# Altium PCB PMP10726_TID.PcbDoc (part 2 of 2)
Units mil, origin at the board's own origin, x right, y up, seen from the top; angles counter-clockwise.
Board outline 1200 x 2800 mil, 4 copper layers (Top Layer, Inner Layer 1, Inner Layer 2, Bottom Layer), stack 60.2 mil thick; 86 components, 43 nets, 209 pads, 170 vias.
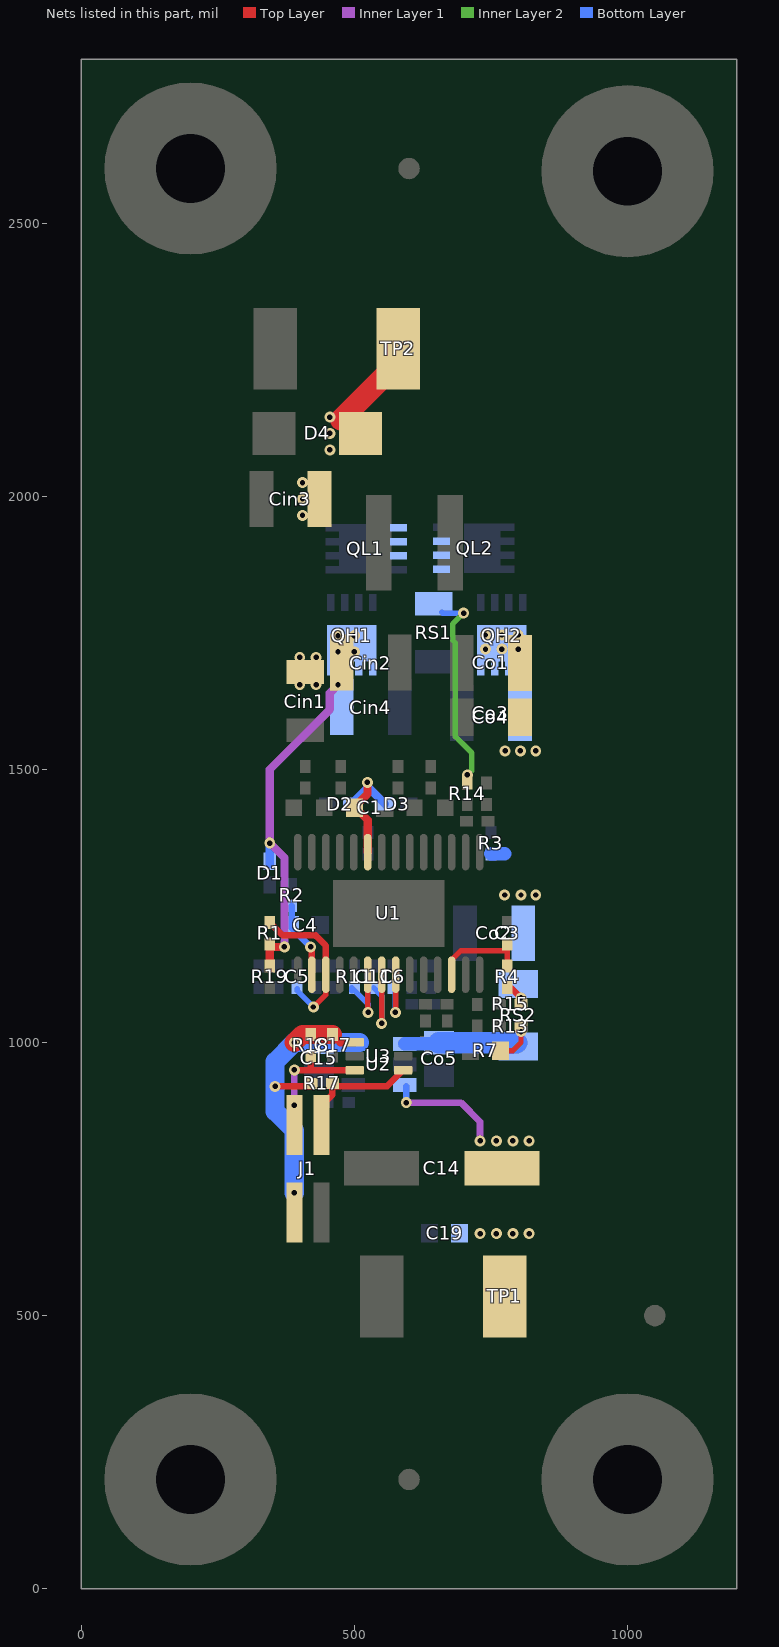
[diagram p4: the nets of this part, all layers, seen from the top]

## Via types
v1: diameter 20, hole 10, Top Layer to Bottom Layer, 93 vias
v2: diameter 20, hole 10, Top Layer to Bottom Layer, tented both sides, 77 vias

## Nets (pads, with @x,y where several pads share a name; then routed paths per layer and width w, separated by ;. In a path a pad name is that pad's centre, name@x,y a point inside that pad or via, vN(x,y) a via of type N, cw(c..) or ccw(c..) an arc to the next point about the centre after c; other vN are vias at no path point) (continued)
PP_IN: Cin1.1 Cin2.1 Cin3.1 Cin4.1 D1.2 D4.1 QH1.5 QH1.6 QH1.7 QH1.8 QH1.9 R1.2 R19.1 TP2.1 | length 758.4
  Top Layer w15: R19.1@345,1139.68 R1.2@345,1180.31 ; R1.2@350.31,1175 v2(371.87,1175)
  Top Layer w40: D4.1@475,2140 TP2.1@556.26,2221.26
  Inner Layer 1 w15: v2(371.87,1175) 371.87,1338.19 345,1365.06 345,1500 455,1610 455,1640 v1(470,1655)
  Bottom Layer w15: D1.2@345,1326.65 D1.2@345,1331.65 v1(345,1365)
  other v1: 400,1655 430,1655 400,1705 430,1705 470,1715 500,1715 470,1745 500,1745 405,1965 405,1995 405,2025 455,2085 455,2115 455,2145
PP_OUT: C14.1 C19.2 Co5.1 R7.2 R13.1 RS2.2 TP1.1 U2.1 U2.3 | length 474.5
  Top Layer w10: R7.2@767.56,985 790,985 805,1000 v1(805,1020)
  Inner Layer 1 w12: v1(595,890) 695,890 730,855 v2(730,820)
  Bottom Layer w12: v1(595,890) U2.3@595,919.84
  Bottom Layer w25: U2.1@592.24,997.4 Co5.1@647.13,997.4
  Bottom Layer w40: Co5.1@655,999.53 RS2.2@796.61,999.53
  other v2: 730,650 760,650 790,650 820,650 760,820 790,820 820,820
RT: R11.1 U1.6 | length 127.4
  Top Layer w10: U1.6@524.43,1124.09 524.43,1064.43 525,1063.86 v1@525,1060
  Bottom Layer w10: R11.1@495,1095 495,1100.31 497.5,1097.82 525,1070.31 v1(525,1055)
SCL: J1.2 R18.1 U3.3 | length 205.1
  Top Layer w12: v1(390,950) 390.59,949.41 U3.3@500.71,949.41 ; 420,950.32 R18.1@420,975.32
  Inner Layer 1 w12: v1(390,885) 395,890 390,895 v1(390,950)
SDA: J1.4 R17.1 U3.4 | length 229.8
  Top Layer w12: J1.4@440,840.12 J1.4@440,849.12 440,885 459.68,904.68 459.68,920 559.88,920 U3.4@589.29,949.41
SLOPE: C11.1 U1.7 | length 150.6
  Top Layer w10: 550,1045 U1.7@550.02,1124.09
  Bottom Layer w10: C11.1@535,1100.32 550,1085.32 v1(550,1035)
SS: C6.2 U1.8 | length 108
  Top Layer w10: v1@575.61,1060.61 U1.8@575.61,1124.09 U1.8@575.61,1133.31
  Bottom Layer w10: v1@575,1060 C6.2@575,1095.31
  other v1: 575,1055
SYSTEM_3V3: C15.2 C17.2 J1.1 R17.2 R18.2 U2.5 U3.1 | length 611.5
  Top Layer w12: v1@355,920 R17.2@420.31,920
  Top Layer w15: C17.2@460,1014.69 474.09,1000.59 U3.1@500.71,1000.59
  Top Layer w35: v1(390,1000) 404.69,1014.69 R18.2@420,1014.69 C17.2@460,1014.69
  Bottom Layer w35: v1(390,725) 390,839.04 355,874.04 v1(355,919.52) 355,965 v1(390,1000) 435,1000 497.76,1000 U2.5@509.57,1000
VCC: C1.1 D2.2 D3.2 U1.23 | length 245.5
  Top Layer w15: v1(523.82,1476.3) 523.82,1454.86 500.26,1431.3 501,1430.56 524.43,1407.13 U1.23@524.43,1348.5
  Bottom Layer w15: D2.2@494.47,1436.3 523.82,1465.65 v1@523.82,1468.65 ; v1(523.82,1476.3) v1@523.82,1468.65 ; D3.2@556.16,1436.3 v1@523.82,1468.65
VIN_IC: C4.2 R2.1 U1.2 | length 138.7
  Top Layer w12: U1.2@422.07,1124.09 v2@422.07,1172.93
  Bottom Layer w12: R2.1@385,1250.32 385,1215 385,1210 v2(420,1175)
VINSNS: C5.2 R1.1 U1.3 | length 291.8
  Top Layer w10: v1(425,1065) 447.66,1087.66 U1.3@447.66,1124.09
  Top Layer w12: R1.1@345,1219.68 368.68,1196 428.7,1196 ; U1.3@447.66,1124.09 447.66,1177.34 430,1195 ; 428.7,1196 429,1196 430,1195 ; 428.7,1196 429.7,1195 430,1195
  Bottom Layer w10: C5.2@395,1098.35 395,1095 v1(425,1065) ; v1@428.35,1065 v1@430,1063.35
VOSNS: C3.2 R4.1 U1.12 | length 173.7
  Top Layer w10: U1.12@677.97,1124.09 677.97,1151.46 694.82,1168.3 776.7,1168.3 ; R4.1@780,1139.68 C3.2@780,1180.31
VOUT: Co1.1 Co2.1 Co3.1 Co4.1 QH2.5 QH2.6 QH2.7 QH2.8 QH2.9 R3.2 R4.2 R15.1 RS2.1 | length 50.9
  Top Layer w12: R4.2@786.5,1100.31 v1(805,1081.81)
  Bottom Layer w25: R3.2@750,1345.31 774.69,1345.31
  other v1: 776,1534 804,1534 832,1534 740,1720 770,1720 800,1720 740,1746 770,1746 800,1746
  other v2: 775,1270 805,1270 832,1270
VRS: QL1.1 QL1.2 QL1.3 QL2.1 QL2.2 QL2.3 R14.2 RS1.2 | length 362.8
  Inner Layer 2 w10: v2(700,1786) 680,1766 680,1736.72 685,1731.72 685,1560 715,1530 715,1498.19 v1(706.81,1490)
  Bottom Layer w10: RS1.2@660.2,1787.95 662.15,1786 v2(700,1786)
pads on no net: FID1.1 FID2.1 FID3.1 H1.1 H2.1 H3.1 H4.1

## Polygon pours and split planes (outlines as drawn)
GND on Bottom Layer "Bottom Layer-No Net 5" (solid, remove dead copper, pour order 45): 300,2175 850,2175 850,625 300,625
PP_IN on Bottom Layer "Bottom Layer-No Net 4" (solid, remove dead copper, pour order 38): 550,1770 390,1770 390,1560 525,1560 525,1668.15 526.05,1668.15 550,1678.07
HDRV1_N on Bottom Layer "Bottom Layer-No Net 3" (solid, remove dead copper, pour order 36): 640,2175 640,1970 615,1970 615,1955 545,1955 545,1830 525.55,1830 520,1824.45 520,1780 445,1780 430,1780 430,2030 475,2075 475,2175
VRS on Bottom Layer "Bottom Layer-No Net 2" (solid, remove dead copper, pour order 35): 555,1951 604,1951 629.85,1925.15 685,1925.15 685,1785 605,1785 605,1865 600,1870 555,1870
HDRV2_N on Bottom Layer "Bottom Layer-No Net 1" (solid, remove dead copper, pour order 34): 690,1960 690,1835 720,1805 720,1790 720,1785 795,1785 795,1824.13 790,1829.13 790,1850 800,1860 850,1860 850,2175 650,2175 650,1970 660,1960
VOUT on Bottom Layer "Bottom Layer-No Net" (solid, remove dead copper, pour order 27): 760,1155 760,1080 850,1080 850,1775 720,1775 720,1670.12 759.88,1670.12
PP_OUT on Bottom Layer "Bottom Layer-No Net 6" (solid, remove dead copper, pour order 42): 850,625 705,625 705,1020 850,1020
GND on Inner Layer 1 "Bottom Layer-No Net 5" (solid, remove dead copper, pour order 46): 300,2175 850,2175 850,625 300,625
HDRV2_N on Inner Layer 1 "Inner Layer 2-No Net" (solid, remove dead copper, pour order 40): 850,2175 650,2175 650,1830 790,1830 790,1845 805,1860 850,1860
HDRV1_N on Inner Layer 1 "Top Layer-No Net" (solid, remove dead copper, pour order 30): 615,2175 640,2175 640,2075 640,1970 610,1970 610,1855 575,1855 575,1830 480,1830 480,1992.05 545,2057.05 545,2175
PP_IN on Inner Layer 1 "Top Layer-No Net 1" (solid, remove dead copper, pour order 32): 377.6,1640 488.11,1640 488.11,1665 514.95,1693 515.05,1820 467.6,1820 467.6,1995 477.6,2005 532.68,2060.08 532.68,2175 427.6,2175 417.6,2165 417.6,2070 377.6,2030 377.6,1830
VOUT on Inner Layer 1 "Bottom Layer-No Net" (solid, remove dead copper, pour order 26): 760,1155 760,1080 850,1080 850,1820 720,1820 720,1670.12 759.88,1670.12
GND on Inner Layer 2 "Bottom Layer-No Net 5" (solid, remove dead copper, pour order 43): 300,2175 850,2175 850,625 300,625
HDRV2_N on Inner Layer 2 "Inner Layer 2-No Net" (solid, remove dead copper, pour order 39): 850,2175 650,2175 650,1830 790,1830 790,1845 805,1860 850,1860
HDRV1_N on Inner Layer 2 "Top Layer-No Net" (solid, remove dead copper, pour order 29): 615,2175 640,2175 640,2075 640,1970 610,1970 610,1855 575,1855 575,1830 480,1830 480,1992.05 545,2057.05 545,2175
VOUT on Inner Layer 2 "Bottom Layer-No Net" (solid, remove dead copper, pour order 25): 760,1155 760,1080 850,1080 850,1820 720,1820 720,1670.12 759.88,1670.12
PP_IN on Inner Layer 2 "Bottom Layer-No Net 4" (solid, remove dead copper, pour order 37): 515,1760 390,1760 390,1642.17 515,1642.17
PP_IN on Top Layer "Top Layer-No Net 3" (solid, remove dead copper, pour order 49): 435,2350 620,2350 620,2195 560,2195 560,2183 541.99,2164.99 435,2164.99
GND on Top Layer "Bottom Layer-No Net 5" (solid, remove dead copper, pour order 44): 300,2175 850,2175 850,625 300,625
HDRV1_N on Top Layer "Top Layer-No Net" (solid, remove dead copper, pour order 28): 615,2175 640,2175 640,2075 640,1970 610,1970 610,1855 575,1855 575,1830 480,1830 480,1992.05 559,2071.05 559,2175
HDRV2_N on Top Layer "Top Layer-No Net 2" (solid, remove dead copper, pour order 33): 650,1825 790,1825 790,1850 800,1860 850,1860 850,2175 650,2175
PP_IN on Top Layer "Top Layer-No Net 1" (solid, remove dead copper, pour order 31): 380,1640 514.8,1640 537.76,1675 554.89,1675 554.97,1785.02 525.02,1815 470,1815 470,1995 480,2005 550,2075 550,2175 430,2175 420,2165 420,2070 380,2030 380,1830
VOUT on Top Layer "Bottom Layer-No Net" (solid, remove dead copper, pour order 24): 759.91,1525 850,1525 850,1820 715,1820 715,1670.12 759.88,1670.12
PP_OUT on Top Layer "Bottom Layer-No Net 6" (solid, remove dead copper, pour order 41): 850,625 705,625 705,845 850,845

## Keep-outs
Keep-Out Layer:
  lines w5: -2.5,0 ccw(c0,0) 0,-2.5 ; -2.5,0 ccw(c0,0) 0,-2.5 ; -2.5,0 -2.5,2800 ; -2.5,2800 cw(c0,2800) 0,2802.5 ; -2.5,2800 cw(c0,2800) 0,2802.5 ; 0,-2.5 1200,-2.5 ; 0,2802.5 1200,2802.5 ; 1200,-2.5 ccw(c1200,0) 1202.5,0 ; 1200,-2.5 ccw(c1200,0) 1202.5,0 ; 1200,2802.5 cw(c1200,2800) 1202.5,2800 ; 1200,2802.5 cw(c1200,2800) 1202.5,2800 ; 1202.5,0 1202.5,2800
  text ".Layer_Name" at 577,-858.49 h60

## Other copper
Top Layer:
  rectangle net GND: 299.29,2175 404.32,2350
  rectangle net GND: 490,450 610,625
  rectangle net PP_OUT: 705,450 850,625
  text ".Layer_Name" at 577,-858.49 h60
Inner Layer 1:
  text ".Layer_Name" at 577,-858.49 h60
Inner Layer 2:
  text ".Layer_Name" at 577,-858.49 h60
Bottom Layer:
  text ".Layer_Name" at 577,-858.49 h60

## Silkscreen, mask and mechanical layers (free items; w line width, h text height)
Top Overlay:
  lines w10: 300,625 300,2175 850,2175 850,625 300,625
  text "TI" at 1079.82,1008.16 h60 r90
  text "SCL" at 355,826 h20 r90
  text "SDA" at 489,824 h20 r90
  text ".CopyrightYear" at 1079.82,732.16 h60 r90
  text "GND" at 489,670 h20 r90
  text "3.3V" at 355,660 h20 r90
  text "©" at 1083.34,615.16 h105 r90
  text ".Layer_Name" at 577,-858.49 h60
Bottom Overlay:
  lines w10: 300,625 850,625 850,2175 300,2175 300,625
  text "UL94V-0" at 975,2170 h60 r90
  text "MADE IN U.S." at 1075,2170 h60 r90
  text ".Layer_Name" at 577,-858.49 h60
Top Paste:
  text ".Layer_Name" at 577,-858.49 h60
Bottom Paste:
  text ".Layer_Name" at 577,-858.49 h60
Top Solder:
  text ".Layer_Name" at 577,-858.49 h60
  text ".Layer_Name" at 577,-858.49 h60
Bottom Solder:
  text ".Layer_Name" at 577,-858.49 h60
Drill Guide:
  text ".Layer_Name" at 577,-858.49 h60
Mechanical 1:
  the board outline again, w10
  text ".Layer_Name" at 577,-858.49 h60
Mechanical 2:
  rectangle: 125,-400 500,-275
  rectangle: 0,-275 125,-150
  lines w7: 0,-275 1000,-275 ; 125,-400 125,-150 ; 250,-400 250,-150 ; 500,-400 500,-150 ; 750,-400 750,-150 ; 0,-400 0,-150 1000,-150 1000,-400 0,-400
  text ".Layer_Name" at 577,-858.49 h60
Mechanical 3:
  text ".Layer_Name" at 577,-858.49 h60
Mechanical 4:
  text ".Layer_Name" at 577,-858.49 h60
Mechanical 5:
  lines w10: -292,-930.17 6308,-930.17 ; -292,-726.83 6310,-726.83 ; -292,-523.5 -292,-1133.5 3713,-1133.5 6310,-1133.5 6310,-523.5 -291.5,-523.5 -291.5,-1133.5 1284,-1133.5 ; 2173,-1133.5 2173,-523.5 ; 3440,-726.83 3440,-523.5 ; 4280,-726.83 4280,-523.5 ; 4902,-1140 4902,-937.17
  text "COMPONENTS MARKED 'DNP' SHOULD NOT BE POPULATED." at 1153.5,-318.5 h60
  text "ASSEMBLY VARIANT:" at 1153,-434 h60
  text ".VariantName" at 2189,-434 h60
  text "PCB VIEWED FROM TOP SIDE" at -228.5,-655.67 h60
  text "BOARD #:" at 2248,-655.67 h60
  text ".PRJ_Number" at 2793.5,-655.67 h60
  text "REV:" at 3638,-655.67 h60
  text ".PCB_Rev" at 3929.5,-655.67 h60
  text "SVN REV:" at 4476,-655.67 h60
  text ".VersionControl_RevNumber" at 4982,-655.67 h60
  text "TID #:" at 2248,-859 h60
  text ".TID" at 2793.5,-859 h60
  text "PLOT NAME =" at -228.5,-1064.34 h60
  text ".plot_File_Name" at 577,-1064.34 h60
  text "GENERATED    :" at 2250,-1064.34 h60
  text ".Print_Date" at 3119.5,-1064.34 h60
  text ".Print_Time" at 3848.5,-1064.34 h60
  text "TEXAS INSTRUMENTS" at 5113,-1064.34 h60
Mechanical 6:
  lines w10: -292.5,-727.33 6309.5,-727.33 ; -290.5,-930.67 6309.5,-930.67 ; 1115.5,-1140.5 1115.5,-937.67 ; 1737.5,-727.33 1737.5,-524 ; 2577.5,-727.33 2577.5,-524 ; 3844.5,-1134 3844.5,-524 ; 4733.5,-1134 6309,-1134 6309,-524 -292.5,-524 -292.5,-1134 2304.5,-1134 6309.5,-1134 6309.5,-524
  text "COMPONENTS MARKED 'DNP' SHOULD NOT BE POPULATED." at 6102,-318 h60
  text ".VariantName" at 5058,-434 h60
  text "ASSEMBLY VARIANT:" at 6097,-434 h60
  text ".VersionControl_RevNumber" at 1035.5,-656.17 h60
  text "SVN REV:" at 1541.5,-656.17 h60
  text ".PCB_Rev" at 2088,-656.17 h60
  text "REV:" at 2379.5,-656.17 h60
  text ".PRJ_Number" at 3224,-656.17 h60
  text "BOARD #:" at 3769.5,-656.17 h60
  text "PCB VIEWED FROM BOTTOM SIDE" at 6246,-656.17 h60
  text ".PRJ_Number" at 3224,-859.5 h60
  text "TID #:" at 3769.5,-859.5 h60
  text "TEXAS INSTRUMENTS" at 904.5,-1064.84 h60
  text ".Print_Time" at 2169,-1064.84 h60
  text ".Print_Date" at 2898,-1064.84 h60
  text "GENERATED    :" at 3767.5,-1064.84 h60
  text ".plot_File_Name" at 5440.5,-1064.84 h60
  text "PLOT NAME =" at 6246,-1064.84 h60
Mechanical 9:
  drawing of 57 lines, arcs and shapes, not listed
  text "1" at 739.84,8036.5 h70
  text "2" at 3235.5,8036.5 h70
  text "3" at 5724.84,8036.5 h70
  text "4" at 8231.51,8036.5 h70
  text "5" at 10730.5,8036.5 h70
  text "6" at 13235.5,8036.5 h70
  text "A" at -416.5,6893.5 h70
  text "A" at 14383.5,6893.5 h70
  text "B" at -416.5,4513.5 h70
  text "B" at 14383.5,4513.5 h70
  text "C" at -416.5,2138.5 h70
  text "C" at 14383.5,2138.5 h70
  text "PROJECT TITLE:" at 11343.5,277.5 h45
  text ".PRJ_Title" at 11393.5,144.17 h70
  text "DESIGNED FOR:" at 11343.5,-23.5 h45
  text ".PRJ_Customer" at 11393.5,-163.5 h70
  text "D" at -416.5,-231.5 h70
  text "D" at 14383.5,-231.5 h70
  text "FILE NAME:" at 11343.5,-323.5 h45
  text ".PCB_File_Name_No_Path" at 11393.5,-443.5 h70
  text "Texas Instruments (TI) and/or its licensors do not warrant the accuracy or completeness of this specification" at 6374,-605.34 h45
  text "ENGINEER:" at 11343.5,-613.5 h45
  text "LAYOUT BY:" at 12848.5,-613.5 h45
  text "or any information contained therein. TI and/or its licensors do not warrant that this design will meet" at 6329.01,-718 h45
  text ".PRJ_Engineer" at 11393.5,-768.49 h70
  text ".PCB_Layout" at 12899,-768.49 h70
  text "the specifications, will be suitable for your application or fit for any particular purpose, or will operate in" at 6329.01,-830.67 h45
  text ".Layer_Name" at 577,-858.49 h60
  text "ALTIUM DESIGNER VERSION:" at 12848.5,-923.5 h45
  text "an implementation. TI and/or its licensors do not warrant that the design is production worthy. You should" at 6329.01,-943.33 h45
  text "completely validate and test your design implementation to confirm the system functionality for your application." at 6374,-1056 h45
  text ".print_Scale" at 11393.5,-1056.83 h70
  text ".Application_BuildNumber" at 12899,-1056.83 h70
  text "1" at 739.84,-1263.5 h70
  text "2" at 3235.5,-1263.5 h70
  text "3" at 5724.84,-1263.5 h70
  text "4" at 8231.51,-1263.5 h70
  text "5" at 10730.5,-1263.5 h70
  text "6" at 13235.5,-1263.5 h70
Mechanical 10:
  drawing of 185 lines, arcs and shapes, not listed
  text "DESIGN INFORMATION" at 12381.02,5910 h60
  text "MIN. TRACK WIDTH:" at 11736.46,5730 h60
  text "10" at 12832.7,5730 h60
  text "MIL" at 12987.46,5730 h60
  text "MIN. CLEARANCE:" at 11736.46,5598 h60
  text "0.13" at 12772.7,5598 h60
  text "mm" at 12987.46,5598 h60
  text "MIN. VIA PAD SIZE:" at 11736.46,5466 h60
  text "20" at 12802.71,5466 h60
  text "MIL" at 12987.46,5466 h60
  text "0.127mm (5MIL)" at 12431.46,5324.29 h60
  text "MINIMUM ANNULAR RING" at 11407.23,5320 h60
  text "EXTERNAL" at 13139.46,5320 h60
  text "PER" at 11607.23,5202 h60
  text "IPC-D-275 CLASS 2 LEVEL C" at 11827.23,5202 h60
  text "MIL, HOLES" at 13315.46,5089.71 h60
  text "+/-" at 12923,5089 h60
  text "+/-" at 13777,5089 h60
  text "REGISTRATION TOLERANCES:" at 11407.23,5084 h60
  text "METAL" at 12607,5084 h60
  text "5" at 13183.2,5084 h60
  text "3" at 14016.2,5084 h60
  text "MIL" at 14132.46,5084 h60
  text "MATERIAL:" at 11332.46,4874.54 h60
  text "FR-4 High Tg" at 12318.9,4734.21 h60
  text "X" at 13055,4730 h60
  text "FR-408" at 11753.46,4725.64 h60
  text "OTHER" at 13241.46,4725.64 h60
  text "FR-4" at 13643.9,4724.21 h60
  text "62 MIL (1.6mm) +/-10%" at 12073.56,4562.92 h60
  text "THICKNESS:" at 11407.23,4558.64 h60
  text "X" at 11945.4,4558.64 h60
  text "OTHER" at 13358.46,4558.64 h60
  text "TOLERANCE:" at 11407.23,4400.64 h60
  text "X" at 12246.53,4400.64 h60
  text "ANSI IPC-6012 TYPE 3 CLASS 2" at 12433.48,4400.64 h60
  text "OTHER +/-" at 12433.46,4244.64 h60
  text "BOW & TWIST:" at 11407.23,4087.64 h60
  text "X" at 12246.53,4087.64 h60
  text "ANSI IPC-6012 TYPE 3 CLASS 2" at 12433.48,4087.64 h60
  text "OTHER +/-" at 12433.46,3929.13 h60
  text "DRILLING:" at 11332.46,3790.64 h60
  text "REFERENCE:" at 11407.23,3673.64 h60
  text "X" at 12055.46,3673.64 h60
  text "AS SHOWN" at 12242.46,3673.64 h60
  text "X" at 12956.46,3673.64 h60
  text "NC_DRILL FILES" at 13093.46,3673.64 h60
  text "PTH MIN COPPER THICKNESS:" at 11407.23,3515.64 h60
  text "X" at 12757.46,3515.64 h60
  text "1MIL" at 12894.46,3515.64 h60
  text "OTHER" at 13391.46,3515.64 h60
  text "BOARD FINISH:" at 11332.46,3356.64 h60
  text "SILKSCREEN:" at 11487.68,3238.64 h60
  text "X" at 12436.46,3238.64 h60
  text "TOP" at 12562.46,3238.64 h60
  text "X" at 12946.46,3238.64 h60
  text "BOTTOM" at 13073.46,3238.64 h60
  text "SILKSCREEN COLOR:" at 11487.68,3071.64 h60
  text "X" at 12435.42,3071.64 h60
  text "WHITE" at 12562.46,3071.64 h60
  text "OTHER" at 13073.46,3071.64 h60
  text "SOLDER RESIST COLOR:" at 11487.68,2901.64 h60
  text "X" at 12055.42,2742.44 h60
  text "GREEN" at 12182.46,2742.44 h60
  text "BLUE" at 12773.46,2742.44 h60
  text "OTHER" at 13311.46,2742.44 h60
  text "IMMERSION GOLD (ENIG)" at 12393.46,2553.92 h60
  text "ENEPIG" at 13731,2550.64 h60
  text "SURFACE FINISH:" at 11332.46,2549.64 h60
  text "X" at 12206.51,2549.64 h60
  text "IMM. TIN/SILVER OR EQUIV" at 11662,2392.64 h60
  text "OTHER" at 13093.46,2392.64 h60
  text "ARRAY/PANEL:" at 11332.46,2213.64 h60
  text "CUT AND TRIM PER MECH LAYER 1" at 12393.46,2209.35 h60
  text "N.C. ROUTE" at 12393.46,2057.64 h60
  text "X" at 13072.46,2057.64 h60
  text "V. SCORE" at 13259.46,2057.64 h60
  text "CERTIFICATION:" at 11332.46,1920.64 h60
  text "MATERIALS AND WORKMANSHIP FOR ALL PCBS" at 12057.46,1920.64 h60
  text "TO MEET OR EXCEED THE REQUIREMENTS OF:" at 12057.46,1822.64 h60
  text "X" at 11683.96,1686.13 h60
  text "ANSI IPC-A-600F CLASS ->" at 11822.96,1686.13 h60
  text "X" at 13462.02,1686.13 h60
  text "2" at 13580.96,1686.14 h60
  text "1" at 13265.96,1684.64 h60
  text "3" at 13934.96,1684.64 h60
  text "X" at 11686.02,1526.64 h60
  text "UL 94V-0" at 11822.96,1526.64 h60
  text "X" at 12498.02,1526.64 h60
  text "RoHS" at 12634.96,1526.64 h60
  text "OTHER" at 13279.36,1526.64 h60
  text "PER ORDER" at 13676.42,1526.64 h60
  text "ADDITIONAL REQUIREMENTS:" at 11332.46,1385.64 h60
  text "MICROSECTION:" at 11407.23,1270.64 h60
  text "YES" at 12312.96,1270.64 h60
  text "REQUIRED" at 13174.46,1114.49 h60
  text "BARE BOARD ELEC. TEST:" at 11407.23,1111.64 h60
  text "NONE" at 12712.96,1111.64 h60
  text "X" at 13047.46,1111.64 h60
  text "PER ORDER" at 13766.46,1111.64 h60
  text "MANUFACTURER'S UL:" at 11407.23,954.64 h60
  text "RAIL" at 12572.96,950.35 h60
  text "METAL" at 13064.77,950.35 h60
  text "X" at 13440,950 h60
  text "SILK" at 13576.46,950.35 h60
  text ".Layer_Name" at 577,-858.49 h60
Mechanical 11:
  lines w10: -292,-930.17 6308,-930.17 ; -292,-726.83 6310,-726.83 ; -292,-523.5 -292,-1133.5 3713,-1133.5 6310,-1133.5 6310,-523.5 -291.5,-523.5 -291.5,-1133.5 1284,-1133.5 ; 2173,-1133.5 2173,-523.5 ; 3440,-726.83 3440,-523.5 ; 4280,-726.83 4280,-523.5 ; 4902,-1140 4902,-937.17
  text "ALL ARTWORK VIEWED FROM TOP SIDE" at -228.5,-655.67 h60
  text "BOARD #:" at 2248,-655.67 h60
  text ".PRJ_Number" at 2793.5,-655.67 h60
  text "REV:" at 3638,-655.67 h60
  text ".PCB_Rev" at 3929.5,-655.67 h60
  text "SVN REV:" at 4476,-655.67 h60
  text ".VersionControl_RevNumber" at 4982,-655.67 h60
  text "LAYER NAME =" at -228.5,-858.49 h60
  text "TID #:" at 2248,-859 h60
  text ".TID" at 2793.5,-859 h60
  text "PLOT NAME =" at -228.5,-1064.34 h60
  text ".plot_File_Name" at 577,-1064.34 h60
  text "GENERATED    :" at 2250,-1064.34 h60
  text ".Print_Date" at 3119.5,-1064.34 h60
  text ".Print_Time" at 3848.5,-1064.34 h60
  text "TEXAS INSTRUMENTS" at 5113,-1064.34 h60
Mechanical 12:
  drawing of 295 lines, arcs and shapes, not listed
  text "Layer" at 9795.09,7860 h60
  text "Name" at 10205,7860 h60
  text "Material" at 11134.74,7860 h60
  text "Thickness" at 11994.51,7860 h60
  text "Constant" at 12644.35,7860 h60
  text "Board Layer Stack" at 13214.21,7860 h60
  text "1" at 9795.09,7740 h60
  text "Top Overlay" at 10205,7740 h60
  text "2" at 9795.09,7620 h60
  text "Top Solder" at 10205,7620 h60
  text "Solder Resist" at 11134.74,7620 h60
  text "0.50mil" at 11994.51,7620 h60
  text "3.5" at 12644.35,7620 h60
  text "3" at 9795.09,7500 h60
  text "Top Layer" at 10205,7500 h60
  text "Copper" at 11134.74,7500 h60
  text "2.80mil" at 11994.51,7500 h60
  text "4" at 9795.09,7380 h60
  text "Dielectric 1" at 10205,7380 h60
  text "FR-4" at 11134.74,7380 h60
  text "9.10mil" at 11994.51,7380 h60
  text "4.2" at 12644.35,7380 h60
  text "5" at 9795.09,7260 h60
  text "Inner Layer 1" at 10205,7260 h60
  text "Copper" at 11134.74,7260 h60
  text "2.80mil" at 11994.51,7260 h60
  text "6" at 9795.09,7140 h60
  text "Dielectric 2" at 10205,7140 h60
  text "FR-4" at 11134.74,7140 h60
  text "30.80mil" at 11994.51,7140 h60
  text "4.2" at 12644.35,7140 h60
  text "7" at 9795.09,7020 h60
  text "Inner Layer 2" at 10205,7020 h60
  text "Copper" at 11134.74,7020 h60
  text "2.80mil" at 11994.51,7020 h60
  text "8" at 9795.09,6900 h60
  text "Dielectric 3" at 10205,6900 h60
  text "FR-4" at 11134.74,6900 h60
  text "9.10mil" at 11994.51,6900 h60
  text "4.2" at 12644.35,6900 h60
  text "9" at 9795.09,6780 h60
  text "Bottom Layer" at 10205,6780 h60
  text "Copper" at 11134.74,6780 h60
  text "2.80mil" at 11994.51,6780 h60
  text "10" at 9795.09,6660 h60
  text "Bottom Solder" at 10205,6660 h60
  text "Solder Resist" at 11134.74,6660 h60
  text "0.50mil" at 11994.51,6660 h60
  text "3.5" at 12644.35,6660 h60
  text "11" at 9795.09,6540 h60
  text "Bottom Overlay" at 10205,6540 h60
  text ".Layer_Name" at 577,-858.49 h60
Mechanical 13:
  text ".Layer_Name" at 577,-858.49 h60
Mechanical 14:
  text ".Layer_Name" at 577,-858.49 h60
Mechanical 15:
  text ".Layer_Name" at 577,-858.49 h60
Mechanical 16:
  text ".Layer_Name" at 577,-858.49 h60
Drill Drawing:
  circle w10: c1483.72,2491.96 r27.63
  lines w10: 1456.09,2643.91 1511.34,2643.91 1483.72,2588.66 1456.09,2643.91
  lines w12: 1406,2427.04 3384.02,2427.04 ; 1406,2675.68 3384.02,2675.68 ; 1743.86,2302.72 1743.86,2800 ; 2075.86,2302.72 2075.86,2800 ; 2712.43,2302.72 2712.43,2800 ; 2971.57,2302.72 2971.57,2800 ; 1406,2302.72 3384.02,2302.72 3384.02,2800 1406,2800 1406,2302.72
  text "Symbol" at 1480.59,2712.98 h72
  text "Quantity" at 1781.16,2712.98 h72
  text "Finished Hole Size" at 2113.16,2712.98 h72
  text "Plated" at 2749.72,2712.98 h72
  text "Hole Type" at 3008.86,2712.98 h72
  text "170" at 1781.16,2588.66 h60
  text "10.00mil (0.254mm)" at 2113.16,2588.66 h60
  text "PTH" at 2749.72,2588.66 h60
  text "Round" at 3008.86,2588.66 h60
  text "4" at 1781.16,2464.34 h60
  text "125.98mil (3.200mm)" at 2113.16,2464.34 h60
  text "PTH" at 2749.72,2464.34 h60
  text "Round" at 3008.86,2464.34 h60
  text "174 Total" at 1781.16,2340.02 h60
  text ".Layer_Name" at 577,-858.49 h60

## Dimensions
0,0 to 1200,0 on Mechanical 2
0,0 to 0,2800 on Mechanical 2
0,-400 to 1000,-400 on Mechanical 2
300,625 to 850,625 on Top Overlay
850,625 to 850,2175 on Top Overlay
